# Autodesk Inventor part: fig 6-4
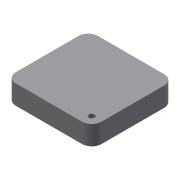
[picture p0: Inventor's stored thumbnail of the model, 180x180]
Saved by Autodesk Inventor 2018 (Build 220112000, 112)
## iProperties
Created: 2004-05
Part Number: fig 6-4
Document SubType Name: Modeling
Designer: CADCIM Technologies
Manufacturer: Standard
Standards Organization: Custom
Density: 1 g/cm^3
Material: Generic
Appearance: Default
Author: CADCIM Technologies
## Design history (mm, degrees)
sketch "Sketch1"
  geometry: L1 (0, 0)-(44.293, 0); L2 (44.293, 0)-(44.293, 42.442); L3 (44.293, 42.442)-(0, 42.442); L4 (0, 42.442)-(0, 0)
  constraints: 8 end point, 2 parallel, 1 horizontal, 1 perpendicular
extrude "Extrusion1" new body sketch "Sketch1" distance "d0" = 10; taper "d1" = 0 deg
fillet "Fillet1" dims "d2" = 5
sketch "Sketch2"
  geometry: 1 further point
sketch "Sketch3"
  geometry: L1 (5, 42.442)-(39.293, 42.442) reference; L2 (0, 5)-(0, 37.442) reference; L3 (39.293, 0)-(5, 0) reference; L4 (44.293, 37.442)-(44.293, 5) reference; A1 r 5 centre (39.293, 37.442) between (44.293, 37.442) and (39.293, 42.442) reference; A2 r 5 centre (5, 37.442) between (5, 42.442) and (0, 37.442) reference; A3 r 5 centre (5, 5) between (0, 5) and (5, 0) reference; A4 r 5 centre (39.293, 5) between (39.293, 0) and (44.293, 5) reference; 1 further point
hole "Hole2" diameter "d15" = 3; stored, may be unused: countersink angle "d19" = 90 deg, drill point angle "d21" = 118 deg; dims "d13" = 10, "d14" = 10, "d16" = 6, "d17" = 4, "d18" = 2, "d20" = 8
body "Solid1"
